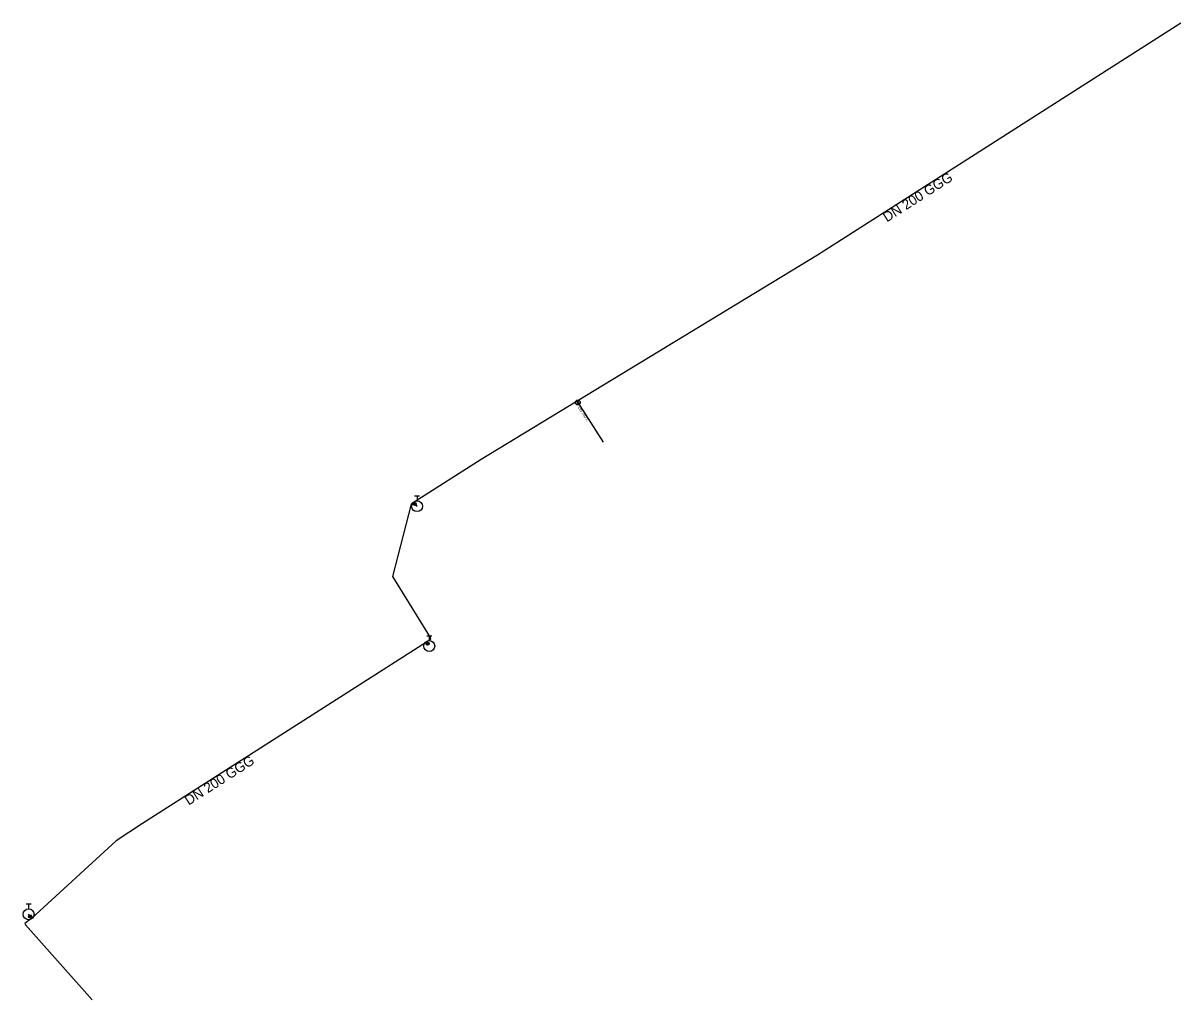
# Model space of a CAD drawing. Extents: x -451501 to -451094, y -1102108 to -1101623.
# Drawn here: x -451282.2 to -451094.1, y -1102107.9 to -1101949.2 of the extents above; entities that cross this region are included whole.
import ezdxf

# ---------------------------------------------------------------- set-up
doc = ezdxf.new("R2010")
doc.units = 0
for name, color, linetype in [('_hydrantova_odbocka_', 7, 'Continuous'), ('_pripojka_priblizne_', 7, 'Continuous'), ('_voda_smvak_prevzato_z_dokumentace_', 7, 'Continuous'), ('Default', 7, 'Continuous'), ('MoLevel 27', 7, 'Continuous'), ('MoLevel 28', 7, 'Continuous'), ('MoLevel 32', 7, 'Continuous'), ('MoLevel 46', 7, 'Continuous'), ('MoLevel 53', 7, 'Continuous')]:
    doc.layers.add(name, color=color, linetype=linetype)

# ---------------------------------------------------------------- blocks, each defined once
blk = doc.blocks.new('_uzaver_')
at = {"layer": 'Default'}
for p, q in [((-0.000035, -0.000035), (0.000035, 0.000035)), ((0.000035, -0.000035), (-0.000035, 0.000035))]:
    blk.add_line(p, q, dxfattribs=at)
for radius in [0.00005, 0.0000025]:
    blk.add_circle((0, 0), radius, dxfattribs=at)
blk = doc.blocks.new('_uzaver_pripojka_')
at = {"layer": 'Default'}
for p, q in [((-0.000035, -0.000035), (0.000035, 0.000035)), ((0.000035, -0.000035), (-0.000035, 0.000035))]:
    blk.add_line(p, q, dxfattribs=at)
for radius in [0.00005, 0.0000025]:
    blk.add_circle((0, 0), radius, dxfattribs=at)
blk = doc.blocks.new('_hydrant_voda_')
at = {"layer": 'Default'}
for p, q in [((-0.000023, 0.000095), (0.000023, 0.000095)), ((0, 0.000095), (0, 0.00005))]:
    blk.add_line(p, q, dxfattribs=at)
blk.add_circle((0, 0), 0.00005, dxfattribs=at)

msp = doc.modelspace()

# ---------------------------------------------------------------- linework, layer by layer
at = {"layer": '_hydrantova_odbocka_'}
for p, q in [((-451218.64, -1102027.02), (-451218.56, -1102027.33)), ((-451218.56, -1102027.33), (-451218.18, -1102027.69)), ((-451281.05, -1102094.37), (-451281.3, -1102094.02)), ((-451280.77, -1102094.65), (-451281.05, -1102094.37))]:
    msp.add_line(p, q, dxfattribs=at)
at = {"layer": '_pripojka_priblizne_'}
msp.add_lwpolyline([(-451192.13, -1102010.59), (-451192.05, -1102010.82), (-451187.91, -1102017.27)], dxfattribs=at)
at = {"layer": '_voda_smvak_prevzato_z_dokumentace_'}
for points in [[(-451094.06, -1101949.15), (-451153.11, -1101986.86), (-451192.13, -1102010.59)], [(-451192.13, -1102010.59), (-451207.74, -1102020.11), (-451218.64, -1102027.02), (-451219.11, -1102027.35), (-451222.17, -1102039.13), (-451216.05, -1102049.02), (-451215.98, -1102049.23), (-451216.12, -1102049.41), (-451216.63, -1102049.77), (-451262.79, -1102079.25), (-451267.08, -1102082.11), (-451280.77, -1102094.65), (-451281.91, -1102095.54), (-451281.81, -1102095.74), (-451270.95, -1102107.94)]]:
    msp.add_lwpolyline(points, dxfattribs=at)

# ---------------------------------------------------------------- block references
at = {"layer": 'MoLevel 27', "xscale": 5000, "yscale": 5000}
for p in [(-451218.56, -1102027.33), (-451216.46, -1102050.04), (-451281.05, -1102094.37)]:
    msp.add_blockref('_uzaver_', p, dxfattribs=at)
at = {"layer": 'MoLevel 28', "xscale": 17636.68430335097, "yscale": 17636.68430335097}
for p in [(-451218.18, -1102027.69), (-451216.18, -1102050.42), (-451281.3, -1102094.02)]:
    msp.add_blockref('_hydrant_voda_', p, dxfattribs=at)
at = {"layer": 'MoLevel 53', "xscale": 8000, "yscale": 7999.999999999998, "rotation": 23.690689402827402}
msp.add_blockref('_uzaver_pripojka_', (-451192.05, -1102010.82), dxfattribs=at)

# ---------------------------------------------------------------- texts
at = {"layer": 'MoLevel 32'}
msp.add_text('DN 200 L', height=0.455, rotation=302.6688, dxfattribs=at).set_placement((-451192.06, -1102011.65))
at = {"layer": 'MoLevel 46'}
for rotation, p in [(32.5605, (-451141.82, -1101981.56)), (32.5643, (-451255.29, -1102076.37))]:
    msp.add_text('DN 200 GGG', height=1.605, rotation=rotation, dxfattribs=at).set_placement(p)

doc.saveas('drawing.dxf')
